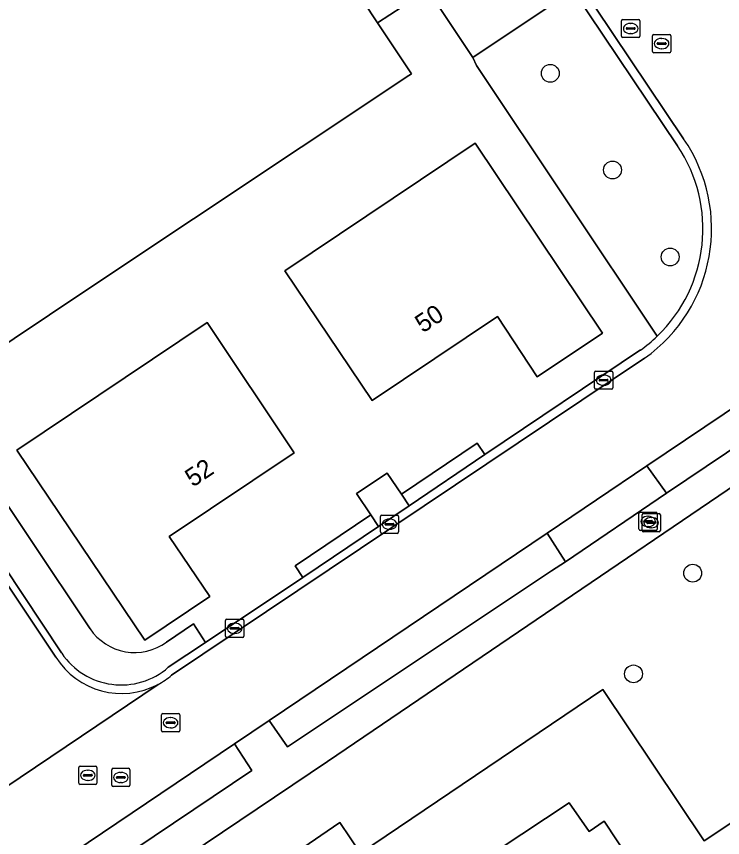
# Model space of a CAD drawing. Extents: x 158793 to 159888, y 384317 to 385256.
# Drawn here: x 159132.88 to 159171.61, y 384582.61 to 384627.65 of the extents above; entities that cross this region are included whole.
import ezdxf

# ---------------------------------------------------------------- set-up
doc = ezdxf.new("R2010")
doc.units = 0
for name, color, linetype in [('IMGEO_Berm_groen', 7, 'Continuous'), ('IMGEO_Boom', 7, 'Continuous'), ('IMGEO_Brandkraan', 7, 'Continuous'), ('IMGEO_Erf', 7, 'Continuous'), ('IMGEO_Groenvoorziening', 7, 'Continuous'), ('IMGEO_Kolk', 7, 'Continuous'), ('IMGEO_Pand', 7, 'Continuous'), ('IMGEO_Pand_nummerreeks', 7, 'Continuous'), ('IMGEO_Parkeervlak_halfverhard', 7, 'Continuous'), ('IMGEO_Rijbaan_lokaal_open', 7, 'Continuous'), ('IMGEO_Rioolput', 7, 'Continuous'), ('IMGEO_Voetpad_gesloten', 7, 'Continuous'), ('IMGEO_Voetpad_open', 7, 'Continuous')]:
    doc.layers.add(name, color=color, linetype=linetype)

msp = doc.modelspace()

# ---------------------------------------------------------------- linework, layer by layer
at = {"layer": 'IMGEO_Berm_groen'}
msp.add_lwpolyline([(159169.136, 384620.552), (159163.415, 384629.083), (159157.911, 384625.402), (159158.124, 384624.961), (159168.019, 384610.104)], dxfattribs=at)
msp.add_lwpolyline([(159145.803, 384586.282), (159144.836, 384587.745), (159122.32, 384572.583), (159121.518, 384572.043), (159122.57, 384570.491), (159138.377, 384581.17), (159138.32, 384581.256)], close=True, dxfattribs=at)
msp.add_arc((159162.374, 384615.991), 8.157, 313.7983, 33.9971, dxfattribs=at)
at = {"layer": 'IMGEO_Boom'}
for centre in [(159162.161, 384624.528), (159165.575, 384619.226), (159168.735, 384614.454), (159169.972, 384597.111), (159166.725, 384591.585)]:
    msp.add_circle(centre, 0.489, dxfattribs=at)
at = {"layer": 'IMGEO_Brandkraan'}
for p, q in [((159167.026, 384599.523), (159167.026, 384600.375)), ((159167.101, 384600.449), (159167.953, 384600.449)), ((159167.197, 384599.452), (159167.197, 384600.304)), ((159167.272, 384600.378), (159168.124, 384600.378)), ((159167.514, 384600.229), (159167.539, 384600.229)), ((159167.685, 384600.158), (159167.71, 384600.158)), ((159168.027, 384600.375), (159168.027, 384599.523)), ((159168.198, 384600.304), (159168.198, 384599.452)), ((159167.285, 384599.943), (159167.285, 384599.955)), ((159167.723, 384599.906), (159167.325, 384599.906)), ((159167.328, 384599.992), (159167.726, 384599.992)), ((159167.456, 384599.872), (159167.456, 384599.884)), ((159167.894, 384599.835), (159167.496, 384599.835)), ((159167.499, 384599.921), (159167.897, 384599.921)), ((159167.769, 384599.955), (159167.769, 384599.943)), ((159167.94, 384599.884), (159167.94, 384599.872)), ((159167.953, 384599.449), (159167.101, 384599.449)), ((159168.124, 384599.378), (159167.272, 384599.378)), ((159167.537, 384599.669), (159167.512, 384599.669)), ((159167.708, 384599.598), (159167.683, 384599.598))]:
    msp.add_line(p, q, dxfattribs=at)
for points in [[(159167.026, 384599.523), (159167.026, 384600.375)], [(159167.101, 384600.449), (159167.953, 384600.449)], [(159167.197, 384599.452), (159167.197, 384600.304)], [(159167.272, 384600.378), (159168.124, 384600.378)], [(159168.027, 384600.375), (159168.027, 384599.523)], [(159168.198, 384600.304), (159168.198, 384599.452)], [(159167.953, 384599.449), (159167.101, 384599.449)], [(159168.124, 384599.378), (159167.272, 384599.378)]]:
    msp.add_lwpolyline(points, dxfattribs=at)
for centre, radius, start, end in [((159167.103, 384600.373), 0.0765, 91.552, 178.448), ((159167.103, 384600.373), 0.0765, 91.552, 178.448), ((159167.274, 384600.302), 0.0765, 91.552, 178.448), ((159167.274, 384600.302), 0.0765, 91.552, 178.448), ((159167.951, 384600.373), 0.0765, 1.552, 88.448), ((159167.951, 384600.373), 0.0765, 1.552, 88.448), ((159168.122, 384600.302), 0.0765, 1.552, 88.448), ((159168.122, 384600.302), 0.0765, 1.552, 88.448), ((159167.325, 384599.952), 0.0403, 85.8775, 175.7526), ((159167.322, 384599.942), 0.0366, 178.938, 274.7102), ((159167.496, 384599.881), 0.0403, 85.8775, 175.7526), ((159167.493, 384599.871), 0.0366, 178.938, 274.7102), ((159167.726, 384599.949), 0.043, 264.8664, 352.4533), ((159167.73, 384599.954), 0.0386, 1.7309, 96.639), ((159167.897, 384599.878), 0.043, 264.8664, 352.4533), ((159167.901, 384599.883), 0.0386, 1.7309, 96.639), ((159167.103, 384599.525), 0.0765, 181.552, 268.448), ((159167.103, 384599.525), 0.0765, 181.552, 268.448), ((159167.274, 384599.454), 0.0765, 181.552, 268.448), ((159167.274, 384599.454), 0.0765, 181.552, 268.448), ((159167.951, 384599.525), 0.0765, 271.552, 358.448), ((159167.951, 384599.525), 0.0765, 271.552, 358.448), ((159168.122, 384599.454), 0.0765, 271.552, 358.448), ((159168.122, 384599.454), 0.0765, 271.552, 358.448)]:
    msp.add_arc(centre, radius, start, end, dxfattribs=at)
for centre, major_axis, ratio, start_param, end_param in [((159167.513, 384599.949), (-0.387, 0.002), 0.722429, 4.712389, 7.853982), ((159167.684, 384599.878), (-0.387, 0.002), 0.722429, 4.712389, 7.853982), ((159167.538, 384599.949), (-0.39, 0.002), 0.717154, 1.570796, 4.712389), ((159167.709, 384599.878), (-0.39, 0.002), 0.717154, 1.570796, 4.712389)]:
    msp.add_ellipse(centre, major_axis=major_axis, ratio=ratio, start_param=start_param, end_param=end_param, dxfattribs=at)
at = {"layer": 'IMGEO_Erf'}
for points in [[(159107.897, 384637.647), (159125.656, 384610.969), (159130.375, 384603.861), (159136.923, 384594.063)], [(159154.724, 384628.639), (159152.688, 384627.303), (159154.552, 384624.503), (159154.401, 384624.402), (159136.687, 384612.612), (159130.743, 384608.655), (159128.114, 384612.605), (159127.367, 384612.108), (159121.328, 384621.181), (159118.838, 384624.921), (159110.182, 384637.924)], [(159158.124, 384624.961), (159157.911, 384625.402), (159155.435, 384629.138)], [(159168.019, 384610.104), (159158.124, 384624.961)], [(159141.112, 384593.332), (159142.593, 384594.324), (159143.245, 384593.307), (159148.586, 384596.881), (159148.164, 384597.509), (159152.323, 384600.305), (159151.541, 384601.475), (159153.212, 384602.591), (159154.003, 384601.438), (159158.157, 384604.24), (159158.576, 384603.618), (159167.111, 384609.352)]]:
    msp.add_lwpolyline(points, dxfattribs=at)
for points in [[(159147.6, 384613.697), (159158.034, 384620.696), (159165.019, 384610.282), (159161.443, 384607.883), (159159.268, 384611.186), (159152.386, 384606.587)], [(159148.125, 384603.718), (159141.255, 384599.119), (159143.485, 384595.829), (159139.922, 384593.444), (159132.915, 384603.851), (159143.351, 384610.853)]]:
    msp.add_lwpolyline(points, close=True, dxfattribs=at)
for centre, radius, start, end in [((159162.196, 384616.211), 8.439, 305.6256, 313.637), ((159139.367, 384595.703), 2.943, 213.8535, 306.3491)]:
    msp.add_arc(centre, radius, start, end, dxfattribs=at)
at = {"layer": 'IMGEO_Groenvoorziening'}
msp.add_lwpolyline([(159173.826, 384607.279), (159167.457, 384602.991), (159168.528, 384601.493), (159183.92, 384611.847)], dxfattribs=at)
for points in [[(159184.844, 384610.474), (159149.937, 384586.778), (159139.375, 384579.667), (159141.123, 384576.932), (159150.625, 384583.433), (159151.747, 384581.759), (159165.041, 384590.724), (159170.605, 384582.437), (159174.689, 384585.159), (159179.297, 384578.512), (159193.347, 384588.107), (159197.808, 384581.483), (159198.988, 384582.307), (159199.249, 384581.925), (159200.917, 384582.98), (159201.158, 384582.618), (159202.847, 384583.73), (159200.329, 384587.446), (159199.667, 384588.43)], [(159154.003, 384601.438), (159153.212, 384602.591), (159151.541, 384601.475), (159152.323, 384600.305), (159152.748, 384599.672), (159154.43, 384600.804)], [(159162.234, 384597.236), (159162.998, 384597.735), (159161.991, 384599.309), (159146.744, 384589.03), (159147.745, 384587.587)], [(159174.848, 384577.908), (159170.678, 384575.093), (159165.114, 384583.512), (159164.29, 384582.941), (159163.188, 384584.508), (159154.051, 384578.453), (159155.852, 384575.778), (159162.529, 384580.264), (159171.232, 384567.261), (159186.801, 384577.691), (159190.856, 384572.121), (159193.655, 384573.965), (159193.8, 384573.756), (159197.584, 384576.354), (159193.706, 384582.105), (159191.156, 384580.471), (159190.067, 384582.131), (159177.557, 384573.685)]]:
    msp.add_lwpolyline(points, close=True, dxfattribs=at)
at = {"layer": 'IMGEO_Kolk'}
for p, q in [((159164.587, 384607.27), (159164.587, 384608.122)), ((159164.662, 384608.196), (159165.514, 384608.196)), ((159165.075, 384607.976), (159165.1, 384607.976)), ((159165.588, 384608.122), (159165.588, 384607.27)), ((159164.846, 384607.69), (159164.846, 384607.702)), ((159165.284, 384607.653), (159164.886, 384607.653)), ((159164.889, 384607.739), (159165.287, 384607.739)), ((159165.098, 384607.416), (159165.073, 384607.416)), ((159165.33, 384607.702), (159165.33, 384607.69)), ((159165.514, 384607.196), (159164.662, 384607.196)), ((159152.842, 384599.369), (159152.842, 384600.221)), ((159152.917, 384600.295), (159153.769, 384600.295)), ((159153.843, 384600.221), (159153.843, 384599.369)), ((159153.101, 384599.789), (159153.101, 384599.801)), ((159153.539, 384599.752), (159153.141, 384599.752)), ((159153.144, 384599.838), (159153.542, 384599.838)), ((159153.33, 384600.075), (159153.355, 384600.075)), ((159153.585, 384599.801), (159153.585, 384599.789)), ((159153.769, 384599.295), (159152.917, 384599.295)), ((159153.353, 384599.515), (159153.328, 384599.515)), ((159144.352, 384593.657), (159144.352, 384594.509)), ((159144.427, 384594.583), (159145.279, 384594.583)), ((159144.84, 384594.363), (159144.865, 384594.363)), ((159145.353, 384594.509), (159145.353, 384593.657)), ((159144.611, 384594.077), (159144.611, 384594.089)), ((159145.049, 384594.04), (159144.651, 384594.04)), ((159144.654, 384594.126), (159145.052, 384594.126)), ((159145.095, 384594.089), (159145.095, 384594.077)), ((159145.279, 384593.583), (159144.427, 384593.583)), ((159144.863, 384593.803), (159144.838, 384593.803))]:
    msp.add_line(p, q, dxfattribs=at)
for points in [[(159164.587, 384607.27), (159164.587, 384608.122)], [(159164.662, 384608.196), (159165.514, 384608.196)], [(159165.588, 384608.122), (159165.588, 384607.27)], [(159165.514, 384607.196), (159164.662, 384607.196)], [(159152.842, 384599.369), (159152.842, 384600.221)], [(159152.917, 384600.295), (159153.769, 384600.295)], [(159153.843, 384600.221), (159153.843, 384599.369)], [(159153.769, 384599.295), (159152.917, 384599.295)], [(159144.352, 384593.657), (159144.352, 384594.509)], [(159144.427, 384594.583), (159145.279, 384594.583)], [(159145.353, 384594.509), (159145.353, 384593.657)], [(159145.279, 384593.583), (159144.427, 384593.583)]]:
    msp.add_lwpolyline(points, dxfattribs=at)
for centre, radius, start, end in [((159164.664, 384608.12), 0.0765, 91.552, 178.448), ((159164.664, 384608.12), 0.0765, 91.552, 178.448), ((159165.512, 384608.12), 0.0765, 1.552, 88.448), ((159165.512, 384608.12), 0.0765, 1.552, 88.448), ((159164.886, 384607.699), 0.0403, 85.8775, 175.7526), ((159164.883, 384607.689), 0.0366, 178.938, 274.7102), ((159165.287, 384607.696), 0.043, 264.8664, 352.4533), ((159165.291, 384607.701), 0.0386, 1.7309, 96.639), ((159164.664, 384607.272), 0.0765, 181.552, 268.448), ((159164.664, 384607.272), 0.0765, 181.552, 268.448), ((159165.512, 384607.272), 0.0765, 271.552, 358.448), ((159165.512, 384607.272), 0.0765, 271.552, 358.448), ((159152.919, 384600.219), 0.0765, 91.552, 178.448), ((159152.919, 384600.219), 0.0765, 91.552, 178.448), ((159153.767, 384600.219), 0.0765, 1.552, 88.448), ((159153.767, 384600.219), 0.0765, 1.552, 88.448), ((159153.141, 384599.798), 0.0403, 85.8775, 175.7526), ((159153.138, 384599.788), 0.0366, 178.938, 274.7102), ((159153.542, 384599.795), 0.043, 264.8664, 352.4533), ((159153.546, 384599.8), 0.0386, 1.7309, 96.639), ((159152.919, 384599.371), 0.0765, 181.552, 268.448), ((159152.919, 384599.371), 0.0765, 181.552, 268.448), ((159153.767, 384599.371), 0.0765, 271.552, 358.448), ((159153.767, 384599.371), 0.0765, 271.552, 358.448), ((159144.429, 384594.507), 0.0765, 91.552, 178.448), ((159144.429, 384594.507), 0.0765, 91.552, 178.448), ((159145.277, 384594.507), 0.0765, 1.552, 88.448), ((159145.277, 384594.507), 0.0765, 1.552, 88.448), ((159144.651, 384594.086), 0.0403, 85.8775, 175.7526), ((159144.648, 384594.076), 0.0366, 178.938, 274.7102), ((159145.052, 384594.083), 0.043, 264.8664, 352.4533), ((159145.056, 384594.088), 0.0386, 1.7309, 96.639), ((159144.429, 384593.659), 0.0765, 181.552, 268.448), ((159144.429, 384593.659), 0.0765, 181.552, 268.448), ((159145.277, 384593.659), 0.0765, 271.552, 358.448), ((159145.277, 384593.659), 0.0765, 271.552, 358.448)]:
    msp.add_arc(centre, radius, start, end, dxfattribs=at)
for centre, major_axis, ratio, start_param, end_param in [((159165.074, 384607.696), (-0.387, 0.002), 0.722429, 4.712389, 7.853982), ((159165.099, 384607.696), (-0.39, 0.002), 0.717154, 1.570796, 4.712389), ((159153.329, 384599.795), (-0.387, 0.002), 0.722429, 4.712389, 7.853982), ((159153.354, 384599.795), (-0.39, 0.002), 0.717154, 1.570796, 4.712389), ((159144.839, 384594.083), (-0.387, 0.002), 0.722429, 4.712389, 7.853982), ((159144.864, 384594.083), (-0.39, 0.002), 0.717154, 1.570796, 4.712389)]:
    msp.add_ellipse(centre, major_axis=major_axis, ratio=ratio, start_param=start_param, end_param=end_param, dxfattribs=at)
at = {"layer": 'IMGEO_Pand'}
for points in [[(159154.401, 384624.402), (159154.552, 384624.503), (159152.688, 384627.303), (159151.902, 384628.484), (159152.616, 384628.959), (159146.597, 384638.002), (159121.328, 384621.181), (159127.367, 384612.108), (159128.114, 384612.605), (159130.743, 384608.655), (159136.687, 384612.612)], [(159158.034, 384620.696), (159147.6, 384613.697), (159152.386, 384606.587), (159159.268, 384611.186), (159161.443, 384607.883), (159165.019, 384610.282)], [(159143.351, 384610.853), (159132.915, 384603.851), (159139.922, 384593.444), (159143.485, 384595.829), (159141.255, 384599.119), (159148.125, 384603.718)]]:
    msp.add_lwpolyline(points, close=True, dxfattribs=at)
at = {"layer": 'IMGEO_Parkeervlak_halfverhard'}
msp.add_lwpolyline([(159168.528, 384601.493), (159167.457, 384602.991), (159164.688, 384601.127), (159161.991, 384599.309), (159162.998, 384597.735)], close=True, dxfattribs=at)
at = {"layer": 'IMGEO_Rijbaan_lokaal_open'}
for points in [[(159132.904, 384674.594), (159142.977, 384659.569), (159151.786, 384646.421), (159151.816, 384646.386), (159153.659, 384643.618), (159153.675, 384643.594), (159162.493, 384630.457), (159163.415, 384629.083), (159169.136, 384620.552)], [(159169.474, 384620.932), (159143.376, 384659.836), (159133.301, 384674.864)], [(159133.301, 384674.864), (159143.376, 384659.836), (159169.474, 384620.932)], [(159135.37, 384592.715), (159135.349, 384592.747), (159116.512, 384621.153), (159116.103, 384620.885), (159135.039, 384592.506)], [(159135.039, 384592.506), (159116.103, 384620.885)], [(159167.111, 384609.352), (159158.576, 384603.618), (159154.43, 384600.804), (159152.748, 384599.672), (159148.586, 384596.881), (159143.245, 384593.307), (159141.215, 384591.948)], [(159141.396, 384591.513), (159167.331, 384608.9)], [(159167.331, 384608.9), (159141.396, 384591.513)], [(159140.653, 384591.012), (159130.548, 384584.195), (159119.566, 384576.775), (159122.32, 384572.583), (159144.836, 384587.745), (159146.744, 384589.03), (159161.991, 384599.309), (159164.688, 384601.127), (159167.457, 384602.991), (159173.826, 384607.279)], [(159130.548, 384584.195), (159140.653, 384591.012)]]:
    msp.add_lwpolyline(points, dxfattribs=at)
for centre, radius, start, end in [((159162.314, 384616), 8.694, 305.2419, 34.5601), ((159162.314, 384616), 8.694, 305.2419, 34.5601), ((159162.374, 384615.991), 8.157, 313.7983, 33.9971), ((159162.196, 384616.211), 8.439, 305.6256, 313.637), ((159138.65, 384594.781), 4.268, 212.2092, 297.9865), ((159138.65, 384594.781), 4.268, 212.2092, 297.9865), ((159138.631, 384594.914), 3.934, 213.9951, 311.0532), ((159138.665, 384594.762), 4.245, 297.9321, 310.051), ((159138.665, 384594.762), 4.245, 297.9321, 310.051)]:
    msp.add_arc(centre, radius, start, end, dxfattribs=at)
at = {"layer": 'IMGEO_Rioolput'}
for p, q in [((159166.071, 384626.559), (159166.071, 384627.411)), ((159166.146, 384627.485), (159166.998, 384627.485)), ((159166.559, 384627.265), (159166.584, 384627.265)), ((159167.072, 384627.411), (159167.072, 384626.559)), ((159166.33, 384626.979), (159166.33, 384626.991)), ((159166.768, 384626.942), (159166.37, 384626.942)), ((159166.373, 384627.028), (159166.771, 384627.028)), ((159166.814, 384626.991), (159166.814, 384626.979)), ((159166.998, 384626.485), (159166.146, 384626.485)), ((159166.582, 384626.705), (159166.557, 384626.705)), ((159167.767, 384625.732), (159167.767, 384626.584)), ((159167.842, 384626.658), (159168.694, 384626.658)), ((159168.255, 384626.438), (159168.28, 384626.438)), ((159168.768, 384626.584), (159168.768, 384625.732)), ((159168.026, 384626.152), (159168.026, 384626.164)), ((159168.464, 384626.115), (159168.066, 384626.115)), ((159168.069, 384626.201), (159168.467, 384626.201)), ((159168.278, 384625.878), (159168.253, 384625.878)), ((159168.51, 384626.164), (159168.51, 384626.152)), ((159168.694, 384625.658), (159167.842, 384625.658)), ((159140.915, 384589.406), (159141.767, 384589.406)), ((159140.84, 384588.48), (159140.84, 384589.332)), ((159141.099, 384588.9), (159141.099, 384588.912)), ((159141.142, 384588.949), (159141.54, 384588.949)), ((159141.328, 384589.186), (159141.353, 384589.186)), ((159141.583, 384588.912), (159141.583, 384588.9)), ((159141.841, 384589.332), (159141.841, 384588.48)), ((159141.537, 384588.863), (159141.139, 384588.863)), ((159141.351, 384588.626), (159141.326, 384588.626)), ((159141.767, 384588.406), (159140.915, 384588.406)), ((159136.301, 384585.599), (159136.301, 384586.451)), ((159136.376, 384586.525), (159137.228, 384586.525)), ((159136.789, 384586.305), (159136.814, 384586.305)), ((159137.302, 384586.451), (159137.302, 384585.599)), ((159138.11, 384585.48), (159138.11, 384586.332)), ((159138.185, 384586.406), (159139.037, 384586.406)), ((159139.111, 384586.332), (159139.111, 384585.48)), ((159136.56, 384586.019), (159136.56, 384586.031)), ((159136.998, 384585.982), (159136.6, 384585.982)), ((159136.603, 384586.068), (159137.001, 384586.068)), ((159136.812, 384585.745), (159136.787, 384585.745)), ((159137.044, 384586.031), (159137.044, 384586.019)), ((159138.369, 384585.9), (159138.369, 384585.912)), ((159138.807, 384585.863), (159138.409, 384585.863)), ((159138.412, 384585.949), (159138.81, 384585.949)), ((159138.598, 384586.186), (159138.623, 384586.186)), ((159138.853, 384585.912), (159138.853, 384585.9)), ((159137.228, 384585.525), (159136.376, 384585.525)), ((159139.037, 384585.406), (159138.185, 384585.406)), ((159138.621, 384585.626), (159138.596, 384585.626))]:
    msp.add_line(p, q, dxfattribs=at)
for points in [[(159166.071, 384626.559), (159166.071, 384627.411)], [(159166.146, 384627.485), (159166.998, 384627.485)], [(159167.072, 384627.411), (159167.072, 384626.559)], [(159166.998, 384626.485), (159166.146, 384626.485)], [(159167.767, 384625.732), (159167.767, 384626.584)], [(159167.842, 384626.658), (159168.694, 384626.658)], [(159168.768, 384626.584), (159168.768, 384625.732)], [(159168.694, 384625.658), (159167.842, 384625.658)], [(159140.915, 384589.406), (159141.767, 384589.406)], [(159140.84, 384588.48), (159140.84, 384589.332)], [(159141.841, 384589.332), (159141.841, 384588.48)], [(159141.767, 384588.406), (159140.915, 384588.406)], [(159136.301, 384585.599), (159136.301, 384586.451)], [(159136.376, 384586.525), (159137.228, 384586.525)], [(159137.302, 384586.451), (159137.302, 384585.599)], [(159138.11, 384585.48), (159138.11, 384586.332)], [(159138.185, 384586.406), (159139.037, 384586.406)], [(159139.111, 384586.332), (159139.111, 384585.48)], [(159137.228, 384585.525), (159136.376, 384585.525)], [(159139.037, 384585.406), (159138.185, 384585.406)]]:
    msp.add_lwpolyline(points, dxfattribs=at)
for centre, radius, start, end in [((159166.148, 384627.409), 0.0765, 91.552, 178.448), ((159166.148, 384627.409), 0.0765, 91.552, 178.448), ((159166.996, 384627.409), 0.0765, 1.552, 88.448), ((159166.996, 384627.409), 0.0765, 1.552, 88.448), ((159166.37, 384626.988), 0.0403, 85.8775, 175.7526), ((159166.367, 384626.978), 0.0366, 178.938, 274.7102), ((159166.771, 384626.985), 0.043, 264.8664, 352.4533), ((159166.775, 384626.99), 0.0386, 1.7309, 96.639), ((159166.148, 384626.561), 0.0765, 181.552, 268.448), ((159166.148, 384626.561), 0.0765, 181.552, 268.448), ((159166.996, 384626.561), 0.0765, 271.552, 358.448), ((159166.996, 384626.561), 0.0765, 271.552, 358.448), ((159167.844, 384626.582), 0.0765, 91.552, 178.448), ((159167.844, 384626.582), 0.0765, 91.552, 178.448), ((159168.692, 384626.582), 0.0765, 1.552, 88.448), ((159168.692, 384626.582), 0.0765, 1.552, 88.448), ((159168.066, 384626.161), 0.0403, 85.8775, 175.7526), ((159168.063, 384626.151), 0.0366, 178.938, 274.7102), ((159168.467, 384626.158), 0.043, 264.8664, 352.4533), ((159168.471, 384626.163), 0.0386, 1.7309, 96.639), ((159167.844, 384625.734), 0.0765, 181.552, 268.448), ((159167.844, 384625.734), 0.0765, 181.552, 268.448), ((159168.692, 384625.734), 0.0765, 271.552, 358.448), ((159168.692, 384625.734), 0.0765, 271.552, 358.448), ((159140.917, 384589.33), 0.0765, 91.552, 178.448), ((159140.917, 384589.33), 0.0765, 91.552, 178.448), ((159141.765, 384589.33), 0.0765, 1.552, 88.448), ((159141.765, 384589.33), 0.0765, 1.552, 88.448), ((159141.139, 384588.909), 0.0403, 85.8775, 175.7526), ((159141.136, 384588.899), 0.0366, 178.938, 274.7102), ((159141.54, 384588.906), 0.043, 264.8664, 352.4533), ((159141.544, 384588.911), 0.0386, 1.7309, 96.639), ((159140.917, 384588.482), 0.0765, 181.552, 268.448), ((159140.917, 384588.482), 0.0765, 181.552, 268.448), ((159141.765, 384588.482), 0.0765, 271.552, 358.448), ((159141.765, 384588.482), 0.0765, 271.552, 358.448), ((159136.378, 384586.449), 0.0765, 91.552, 178.448), ((159136.378, 384586.449), 0.0765, 91.552, 178.448), ((159137.226, 384586.449), 0.0765, 1.552, 88.448), ((159137.226, 384586.449), 0.0765, 1.552, 88.448), ((159138.187, 384586.33), 0.0765, 91.552, 178.448), ((159138.187, 384586.33), 0.0765, 91.552, 178.448), ((159139.035, 384586.33), 0.0765, 1.552, 88.448), ((159139.035, 384586.33), 0.0765, 1.552, 88.448), ((159136.6, 384586.028), 0.0403, 85.8775, 175.7526), ((159136.597, 384586.018), 0.0366, 178.938, 274.7102), ((159137.001, 384586.025), 0.043, 264.8664, 352.4533), ((159137.005, 384586.03), 0.0386, 1.7309, 96.639), ((159138.409, 384585.909), 0.0403, 85.8775, 175.7526), ((159138.406, 384585.899), 0.0366, 178.938, 274.7102), ((159138.81, 384585.906), 0.043, 264.8664, 352.4533), ((159138.814, 384585.911), 0.0386, 1.7309, 96.639), ((159136.378, 384585.601), 0.0765, 181.552, 268.448), ((159136.378, 384585.601), 0.0765, 181.552, 268.448), ((159137.226, 384585.601), 0.0765, 271.552, 358.448), ((159137.226, 384585.601), 0.0765, 271.552, 358.448), ((159138.187, 384585.482), 0.0765, 181.552, 268.448), ((159138.187, 384585.482), 0.0765, 181.552, 268.448), ((159139.035, 384585.482), 0.0765, 271.552, 358.448), ((159139.035, 384585.482), 0.0765, 271.552, 358.448)]:
    msp.add_arc(centre, radius, start, end, dxfattribs=at)
for centre, major_axis, ratio, start_param, end_param in [((159166.558, 384626.985), (-0.387, 0.002), 0.722429, 4.712389, 7.853982), ((159166.583, 384626.985), (-0.39, 0.002), 0.717154, 1.570796, 4.712389), ((159168.254, 384626.158), (-0.387, 0.002), 0.722429, 4.712389, 7.853982), ((159168.279, 384626.158), (-0.39, 0.002), 0.717154, 1.570796, 4.712389), ((159141.327, 384588.906), (-0.387, 0.002), 0.722429, 4.712389, 7.853982), ((159141.352, 384588.906), (-0.39, 0.002), 0.717154, 1.570796, 4.712389), ((159136.788, 384586.025), (-0.387, 0.002), 0.722429, 4.712389, 7.853982), ((159136.813, 384586.025), (-0.39, 0.002), 0.717154, 1.570796, 4.712389), ((159138.597, 384585.906), (-0.387, 0.002), 0.722429, 4.712389, 7.853982), ((159138.622, 384585.906), (-0.39, 0.002), 0.717154, 1.570796, 4.712389)]:
    msp.add_ellipse(centre, major_axis=major_axis, ratio=ratio, start_param=start_param, end_param=end_param, dxfattribs=at)
at = {"layer": 'IMGEO_Voetpad_gesloten'}
for points in [[(159197.808, 384581.483), (159193.347, 384588.107), (159179.297, 384578.512), (159174.689, 384585.159), (159170.605, 384582.437), (159165.041, 384590.724), (159151.747, 384581.759), (159150.625, 384583.433), (159141.123, 384576.932)], [(159154.051, 384578.453), (159163.188, 384584.508), (159164.29, 384582.941), (159165.114, 384583.512), (159170.678, 384575.093)]]:
    msp.add_lwpolyline(points, dxfattribs=at)
at = {"layer": 'IMGEO_Voetpad_open'}
for points in [[(159136.677, 384657.042), (159137.276, 384656.161), (159138.492, 384654.363), (159140.693, 384651.069), (159141.021, 384650.58), (159142.385, 384648.546), (159146.044, 384643.093), (159146.077, 384643.044), (159148.35, 384639.651), (159154.621, 384630.291), (159153.662, 384629.631), (159153.037, 384629.217), (159152.616, 384628.959), (159151.902, 384628.484), (159152.688, 384627.303), (159154.724, 384628.639), (159155.435, 384629.138), (159157.911, 384625.402), (159163.415, 384629.083), (159162.493, 384630.457), (159162.433, 384630.524)], [(159107.897, 384637.647), (159106.149, 384636.469), (159115.366, 384622.711), (159114.705, 384622.279), (159107.094, 384617.418), (159108.298, 384615.649), (159113.155, 384618.899), (159113.589, 384619.18), (159116.103, 384620.885), (159116.512, 384621.153), (159135.349, 384592.747), (159135.37, 384592.715)], [(159136.923, 384594.063), (159130.375, 384603.861), (159125.656, 384610.969), (159107.897, 384637.647)], [(159173.958, 384626.637), (159183.625, 384612.286), (159183.92, 384611.847), (159168.528, 384601.493), (159162.998, 384597.735), (159162.234, 384597.236), (159147.745, 384587.587), (159146.744, 384589.03), (159144.836, 384587.745), (159145.803, 384586.282), (159138.32, 384581.256), (159138.377, 384581.17), (159139.375, 384579.667), (159149.937, 384586.778), (159184.844, 384610.474)], [(159141.215, 384591.948), (159143.245, 384593.307), (159142.593, 384594.324), (159141.112, 384593.332)]]:
    msp.add_lwpolyline(points, dxfattribs=at)
for points in [[(159158.576, 384603.618), (159158.157, 384604.24), (159154.003, 384601.438), (159154.43, 384600.804)], [(159152.748, 384599.672), (159152.323, 384600.305), (159148.164, 384597.509), (159148.586, 384596.881)]]:
    msp.add_lwpolyline(points, close=True, dxfattribs=at)
for centre, radius, start, end in [((159139.367, 384595.703), 2.943, 213.8535, 306.3491), ((159138.631, 384594.914), 3.934, 213.9951, 311.0532)]:
    msp.add_arc(centre, radius, start, end, dxfattribs=at)

# ---------------------------------------------------------------- texts
at = {"layer": 'IMGEO_Pand_nummerreeks'}
for s, rotation, p in [('50', 33.5581, (159155.172, 384610.257)), ('52', 33.604, (159142.559, 384601.8))]:
    msp.add_text(s, height=1, rotation=rotation, dxfattribs=at).set_placement(p)

doc.saveas('drawing.dxf')
